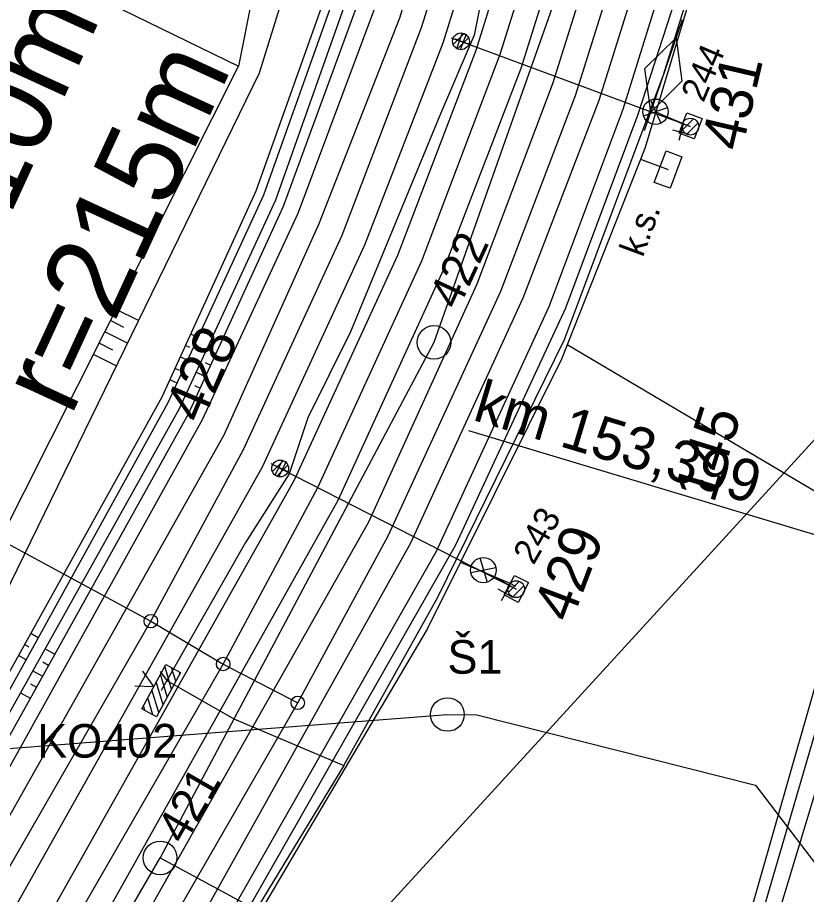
# Model space of a CAD drawing. Extents: x -598638 to -597933, y -1164002 to -1161904.
# Drawn here: x -598318.5 to -598271.6, y -1163425.1 to -1163372.9 of the extents above; entities that cross this region are included whole.
import ezdxf

# ---------------------------------------------------------------- set-up
doc = ezdxf.new("R2010")
doc.units = 0
for name, color, linetype in [('Vrstva 1', 7, 'Continuous'), ('Vrstva 11', 7, 'Continuous'), ('Vrstva 12', 7, 'Continuous'), ('Vrstva 25', 7, 'Continuous'), ('Vrstva 26', 7, 'Continuous'), ('Vrstva 28', 7, 'Continuous'), ('Vrstva 35', 7, 'Continuous'), ('Vrstva 4', 7, 'Continuous'), ('Vrstva 43', 7, 'Continuous'), ('Vrstva 44', 7, 'Continuous'), ('Vrstva 48', 7, 'Continuous'), ('Vrstva 49', 7, 'Continuous'), ('Vrstva 51', 7, 'Continuous'), ('Vrstva 63', 7, 'Continuous'), ('Vrstva 7', 7, 'Continuous')]:
    doc.layers.add(name, color=color, linetype=linetype)

msp = doc.modelspace()

# ---------------------------------------------------------------- linework, layer by layer
at = {"layer": 'Vrstva 1'}
for points in [[(-598310.615, -1163408.802), (-598305.104, -1163398.594), (-598299.235, -1163385.843), (-598294.508, -1163373.505), (-598290.948, -1163362.176)], [(-598306.313, -1163411.351), (-598300.676, -1163400.85), (-598294.505, -1163387.377), (-598289.829, -1163375.091), (-598286.211, -1163363.553)], [(-598301.875, -1163413.661), (-598296.503, -1163403.727), (-598289.8, -1163389.175), (-598285.367, -1163377.539), (-598281.438, -1163365.04)], [(-598373.865, -1163374.549), (-598310.615, -1163408.802), (-598306.313, -1163411.351), (-598301.875, -1163413.661)], [(-598393.834, -1163553.208), (-598373.143, -1163517.281), (-598345.734, -1163469.728), (-598320.048, -1163425.17), (-598310.615, -1163408.802)], [(-598390.948, -1163558.179), (-598390.161, -1163556.813), (-598368.813, -1163519.747), (-598341.41, -1163472.227), (-598315.714, -1163427.65), (-598306.313, -1163411.351)], [(-598386.661, -1163560.816), (-598364.213, -1163521.839), (-598337.049, -1163474.718), (-598311.511, -1163430.389), (-598301.875, -1163413.661)]]:
    msp.add_lwpolyline(points, dxfattribs=at)
for centre in [(-598310.615, -1163408.802), (-598306.313, -1163411.351), (-598301.875, -1163413.661)]:
    msp.add_circle(centre, 0.4, dxfattribs=at)
at = {"layer": 'Vrstva 11'}
for p, q in [((-598292.631, -1163374.504), (-598291.985, -1163373.858)), ((-598292.371, -1163374.774), (-598291.716, -1163374.119)), ((-598278.991, -1163379.574), (-598278.345, -1163378.928)), ((-598278.731, -1163379.844), (-598278.076, -1163379.189)), ((-598303.381, -1163399.904), (-598302.735, -1163399.258)), ((-598303.121, -1163400.174), (-598302.466, -1163399.519)), ((-598289.351, -1163407.084), (-598288.705, -1163406.438)), ((-598289.091, -1163407.354), (-598288.436, -1163406.699))]:
    msp.add_line(p, q, dxfattribs=at)
for points in [[(-598278.53, -1163379.39), (-598292.17, -1163374.32)], [(-598288.89, -1163406.9), (-598302.92, -1163399.72)]]:
    msp.add_lwpolyline(points, dxfattribs=at)
for centre in [(-598292.17, -1163374.32), (-598278.53, -1163379.39), (-598302.92, -1163399.72), (-598288.89, -1163406.9)]:
    msp.add_circle(centre, 0.5, dxfattribs=at)
at = {"layer": 'Vrstva 12'}
for points in [[(-598279.19, -1163379.79), (-598278.73, -1163378.58), (-598277.82, -1163378.91), (-598278.3, -1163380.12), (-598279.19, -1163379.79)], [(-598289.61, -1163407.23), (-598288.98, -1163406.08), (-598288.16, -1163406.51), (-598288.76, -1163407.69), (-598289.61, -1163407.23)]]:
    msp.add_lwpolyline(points, dxfattribs=at)
at = {"layer": 'Vrstva 25'}
for p, q in [((-598281.318, -1163378.742), (-598279.889, -1163378.261)), ((-598280.906, -1163377.814), (-598280.287, -1163379.19)), ((-598279.91, -1163378.802), (-598278.53, -1163379.39)), ((-598291.055, -1163405.046), (-598290.609, -1163406.487)), ((-598291.578, -1163405.916), (-598290.101, -1163405.614)), ((-598290.188, -1163406.148), (-598288.89, -1163406.9))]:
    msp.add_line(p, q, dxfattribs=at)
msp.add_lwpolyline([(-598279.734, -1163383.058), (-598280.671, -1163382.709), (-598279.974, -1163380.834), (-598279.037, -1163381.183), (-598279.734, -1163383.058)], dxfattribs=at)
for centre in [(-598280.603, -1163378.505), (-598290.839, -1163405.768)]:
    msp.add_circle(centre, 0.754, dxfattribs=at)
at = {"layer": 'Vrstva 26'}
for points in [[(-598273.816, -1163355.578), (-598274.288, -1163357.583), (-598281.234, -1163380.697), (-598286.2, -1163393.216), (-598294.185, -1163409.285), (-598301.289, -1163421.306), (-598307.089, -1163431.139)], [(-598280.577, -1163378.511), (-598278.992, -1163379.224), (-598278.678, -1163379.312)], [(-598281.501, -1163381.336), (-598279.854, -1163381.946)], [(-598285.855, -1163392.347), (-598269.505, -1163402.021), (-598268.731, -1163402.266), (-598252.259, -1163406.667), (-598250.635, -1163407.319), (-598251.158, -1163408.595)], [(-598292.202, -1163405.294), (-598289.268, -1163406.549), (-598288.926, -1163406.729)]]:
    msp.add_lwpolyline(points, dxfattribs=at)
at = {"layer": 'Vrstva 28'}
for p, q in [((-598281.259, -1163379.623), (-598279, -1163373.017)), ((-598281.231, -1163375.944), (-598279.377, -1163374.118)), ((-598279.377, -1163374.118), (-598279.028, -1163376.697)), ((-598280.883, -1163378.522), (-598281.231, -1163375.944)), ((-598279.028, -1163376.697), (-598280.883, -1163378.522)), ((-598309.384, -1163412.842), (-598309.789, -1163411.487)), ((-598309.133, -1163412.375), (-598309.375, -1163411.563)), ((-598309.637, -1163413.309), (-598310.041, -1163411.955)), ((-598308.881, -1163411.909), (-598308.909, -1163411.815)), ((-598309.889, -1163413.775), (-598310.294, -1163412.42)), ((-598310.141, -1163414.242), (-598310.546, -1163412.887)), ((-598310.495, -1163414.367), (-598310.798, -1163413.354)), ((-598310.962, -1163414.115), (-598311.05, -1163413.821))]:
    msp.add_line(p, q, dxfattribs=at)
for points in [[(-598280.87, -1163335.69), (-598282.75, -1163342.88), (-598282.94, -1163344.95), (-598283.45, -1163346.41), (-598287.18, -1163358.85), (-598290.82, -1163371.16), (-598291.38, -1163373.96), (-598293.38, -1163378.64), (-598298.74, -1163391.6), (-598301.27, -1163396.71), (-598302.38, -1163400.04), (-598304.98, -1163404.12), (-598309.67, -1163412.34), (-598310, -1163412.93)], [(-598310.06, -1163411.8), (-598309.67, -1163412.34), (-598305.68, -1163414.61), (-598299.13, -1163417.38), (-598293.55, -1163407.38), (-598286.02, -1163392.05), (-598280.13, -1163376.32), (-598275.56, -1163361.58), (-598274.1, -1163355.29), (-598270.65, -1163341.78), (-598271.66, -1163341.69), (-598271.75, -1163341.22)], [(-598311.153, -1163414.012), (-598309.728, -1163411.373), (-598308.848, -1163411.848), (-598310.273, -1163414.487), (-598311.153, -1163414.012)], [(-598311.558, -1163412.657), (-598310.441, -1163412.692), (-598311.082, -1163411.777)], [(-598299.13, -1163417.38), (-598305.71, -1163428.21), (-598313.95, -1163442.64), (-598320.15, -1163459.12), (-598330, -1163482.52), (-598335.96, -1163491.26), (-598347.35, -1163507.42), (-598355.33, -1163518.86), (-598362.35, -1163528.57), (-598373.82, -1163547.05), (-598380.92, -1163559.06), (-598385.36, -1163568.33)]]:
    msp.add_lwpolyline(points, dxfattribs=at)
msp.add_lwpolyline([(-598311.153, -1163414.012), (-598309.728, -1163411.373), (-598308.848, -1163411.848), (-598310.273, -1163414.487)], close=True, dxfattribs=at)
at = {"layer": 'Vrstva 35'}
msp.add_lwpolyline([(-598310.06, -1163411.8), (-598309.67, -1163412.34), (-598305.68, -1163414.61), (-598299.13, -1163417.38)], dxfattribs=at)
at = {"layer": 'Vrstva 4'}
for points in [[(-598398.167, -1163553.239), (-598376.487, -1163515.918), (-598348.795, -1163467.979), (-598339.716, -1163452.202), (-598323.266, -1163423.236), (-598308.372, -1163396.471), (-598302.715, -1163384.123), (-598298.324, -1163372.137), (-598289.593, -1163344.221), (-598282.967, -1163321.229), (-598274.797, -1163290.285), (-598269.404, -1163272.781), (-598266.519, -1163258.633), (-598263.896, -1163241.651), (-598261.185, -1163218.05), (-598260.503, -1163217.001), (-598259.092, -1163201.513), (-598258.163, -1163186.176), (-598256.557, -1163141.317), (-598256.485, -1163129.008), (-598255.651, -1163108.451), (-598254.34, -1163087.718), (-598253.319, -1163075.132)], [(-598307.376, -1163503.64), (-598306.256, -1163500.72), (-598304.527, -1163496.743), (-598299.478, -1163486.144), (-598290.117, -1163465.204), (-598280.795, -1163442.724), (-598274.814, -1163425.66), (-598269.09, -1163405.616), (-598262.907, -1163380.487), (-598260.225, -1163366.071), (-598256.638, -1163342.661), (-598254.612, -1163322.432), (-598252.977, -1163304.928), (-598251.437, -1163287.268), (-598250.068, -1163266.224), (-598248.818, -1163245.446), (-598248.467, -1163214.545), (-598248.623, -1163173.63), (-598248.072, -1163131.254), (-598247.596, -1163128.349)], [(-598388.69, -1163572.819), (-598382.701, -1163561.089), (-598361.383, -1163524.292), (-598334.6, -1163477.579), (-598308.353, -1163432.12), (-598292.471, -1163404.257), (-598285.937, -1163390.16), (-598281.631, -1163378.652), (-598277.216, -1163365.008), (-598272.579, -1163348.284), (-598269.387, -1163336.75), (-598267.113, -1163324.869), (-598262.674, -1163291.919), (-598258.642, -1163259.137), (-598254.182, -1163220.99), (-598251.647, -1163201.068), (-598250.766, -1163187.503), (-598249.671, -1163144.519), (-598248.922, -1163130.776), (-598248.69, -1163130.313)]]:
    msp.add_lwpolyline(points, dxfattribs=at)
at = {"layer": 'Vrstva 43'}
for centre in [(-598293.775, -1163392.227), (-598292.973, -1163414.355), (-598310.061, -1163422.881)]:
    msp.add_circle(centre, 1, dxfattribs=at)
at = {"layer": 'Vrstva 44'}
for points in [[(-598275.426, -1163334.13), (-598284.517, -1163365.994), (-598293.775, -1163392.227), (-598310.061, -1163422.881)], [(-598403.637, -1163432.342), (-598346.555, -1163418.577), (-598345.216, -1163418.65), (-598343.663, -1163418.367), (-598342.098, -1163418.162), (-598292.973, -1163414.355), (-598291.233, -1163414.37), (-598274.654, -1163418.559), (-598263.203, -1163433.575), (-598253.773, -1163465.608), (-598253.123, -1163466.538), (-598245.997, -1163476.61), (-598234.314, -1163480.567), (-598232.066, -1163480.596), (-598231.165, -1163480.525)], [(-598351.577, -1163494.88), (-598326.623, -1163451.361), (-598310.061, -1163422.881), (-598300.732, -1163427.915)]]:
    msp.add_lwpolyline(points, dxfattribs=at)
at = {"layer": 'Vrstva 48'}
for p, q in [((-598311.352, -1163390.931), (-598312.682, -1163390.261)), ((-598312.217, -1163391.335), (-598313.019, -1163390.931)), ((-598312.011, -1163392.279), (-598313.356, -1163391.601)), ((-598307.797, -1163391.928), (-598308.236, -1163391.728)), ((-598312.881, -1163392.68), (-598313.694, -1163392.271)), ((-598308.285, -1163392.53), (-598308.547, -1163392.411)), ((-598307.291, -1163392.638), (-598306.733, -1163392.893)), ((-598312.669, -1163393.627), (-598314.031, -1163392.941)), ((-598308.425, -1163393.29), (-598308.857, -1163393.093)), ((-598308.911, -1163393.893), (-598309.168, -1163393.776)), ((-598307.382, -1163393.421), (-598307.045, -1163393.575)), ((-598307.921, -1163393.999), (-598307.358, -1163394.257)), ((-598309.053, -1163394.653), (-598309.479, -1163394.458)), ((-598308.009, -1163394.784), (-598307.67, -1163394.939)), ((-598308.55, -1163395.361), (-598307.982, -1163395.621)), ((-598317.305, -1163409.786), (-598317.756, -1163409.535)), ((-598317.848, -1163410.342), (-598318.121, -1163410.191)), ((-598316.906, -1163410.444), (-598316.327, -1163410.766)), ((-598318.03, -1163411.099), (-598318.485, -1163410.846)), ((-598317.04, -1163411.228), (-598316.692, -1163411.422)), ((-598317.638, -1163411.754), (-598317.056, -1163412.077)), ((-598317.77, -1163412.538), (-598317.421, -1163412.732)), ((-598318.369, -1163413.063), (-598317.786, -1163413.388))]:
    msp.add_line(p, q, dxfattribs=at)
at = {"layer": 'Vrstva 49'}
for p in [(-598298.967, -1163343.623), (-598322.823, -1163410.399)]:
    msp.add_line(p, (-598305.395, -1163375.792), dxfattribs=at)
for points in [[(-598350.075, -1163469.161), (-598350.962, -1163468.642), (-598341.128, -1163451.449), (-598324.91, -1163422.41), (-598309.936, -1163395.461), (-598304.358, -1163383.215), (-598300.139, -1163371.399), (-598292.224, -1163343.911), (-598285.916, -1163320.98), (-598277.492, -1163289.124), (-598272.642, -1163272.084), (-598269.771, -1163257.778), (-598267.544, -1163241.285), (-598265.728, -1163218.657), (-598264.511, -1163217.412), (-598261.185, -1163218.05)], [(-598350.962, -1163468.642), (-598340.803, -1163451.583), (-598324.406, -1163422.648), (-598309.58, -1163395.796), (-598303.887, -1163383.446), (-598299.666, -1163371.582), (-598291.401, -1163343.859), (-598285.02, -1163321.209), (-598276.751, -1163289.495), (-598271.739, -1163271.843), (-598268.729, -1163258.218), (-598266.553, -1163241.22), (-598264.463, -1163218.64)], [(-598350.075, -1163469.161), (-598340.252, -1163451.87), (-598323.84, -1163422.849), (-598308.915, -1163396.15), (-598303.181, -1163383.749), (-598299.003, -1163371.924), (-598290.374, -1163343.997), (-598283.872, -1163321.586), (-598275.648, -1163289.867), (-598270.185, -1163272.379), (-598267.391, -1163258.396), (-598265.172, -1163241.341), (-598262.635, -1163218.663), (-598264.463, -1163218.64)], [(-598346.31, -1163359.045), (-598341.587, -1163361.65), (-598323.035, -1163367.197), (-598305.395, -1163375.792)], [(-598321.354, -1163411.417), (-598304.154, -1163376.186), (-598299.445, -1163361.058)]]:
    msp.add_lwpolyline(points, dxfattribs=at)
at = {"layer": 'Vrstva 51'}
for points in [[(-598397.431, -1163553.318), (-598375.745, -1163515.943), (-598348.098, -1163468.333), (-598322.38, -1163423.533), (-598307.542, -1163396.818), (-598301.86, -1163384.541), (-598297.285, -1163372.341), (-598293.283, -1163359.379), (-598288.845, -1163344.448), (-598282.25, -1163321.235), (-598273.825, -1163290.423), (-598265.756, -1163258.778), (-598260.545, -1163219.203), (-598259.744, -1163217.171), (-598258.57, -1163201.891), (-598257.659, -1163186.255), (-598256.038, -1163142.193), (-598255.793, -1163128.623), (-598255.065, -1163108.27), (-598253.781, -1163088.998), (-598252.62, -1163075.466)], [(-598396.078, -1163554.151), (-598374.443, -1163516.599), (-598347.031, -1163469.014), (-598321.218, -1163424.261), (-598306.253, -1163397.723), (-598300.608, -1163385.153), (-598295.814, -1163372.93), (-598291.849, -1163359.988), (-598287.46, -1163344.41), (-598281.154, -1163322.32), (-598272.412, -1163291.197), (-598264.229, -1163259.135), (-598258.972, -1163219.27), (-598257.327, -1163201.644), (-598256.369, -1163186.491), (-598254.79, -1163142.649), (-598254.397, -1163128.629), (-598253.571, -1163108.317), (-598252.585, -1163090.153), (-598250.983, -1163076.012)], [(-598384.985, -1163560.822), (-598363.176, -1163523.063), (-598335.955, -1163475.581), (-598310.179, -1163431.066), (-598295.149, -1163404.135), (-598288.465, -1163389.583), (-598283.96, -1163377.815), (-598279.772, -1163364.473), (-598275.196, -1163348.33), (-598271.933, -1163336.198), (-598269.31, -1163324.265), (-598265.084, -1163292.029), (-598261.053, -1163259.678), (-598256.104, -1163220.296), (-598254.426, -1163201.671), (-598253.667, -1163187.936), (-598252.018, -1163143.494), (-598251.534, -1163128.863), (-598250.791, -1163108.998), (-598250.069, -1163094.383), (-598248.218, -1163076.729)], [(-598298.888, -1163486.593), (-598289.113, -1163465.583), (-598279.905, -1163442.964), (-598274.107, -1163425.699), (-598268.268, -1163405.757), (-598262.238, -1163380.596), (-598259.701, -1163366.461), (-598255.999, -1163342.847), (-598253.859, -1163322.319), (-598252.407, -1163304.609), (-598250.982, -1163286.31), (-598249.458, -1163266.6), (-598248.128, -1163245.447), (-598247.963, -1163214.31), (-598248.01, -1163173.778), (-598247.475, -1163130.652), (-598247.596, -1163128.349), (-598246.685, -1163112.866), (-598245.177, -1163096.514), (-598242.921, -1163076.624)], [(-598389.422, -1163572.47), (-598383.242, -1163561.018), (-598361.933, -1163523.985), (-598335.337, -1163477.363), (-598309.065, -1163431.797), (-598293.626, -1163404.644), (-598286.924, -1163390.082), (-598282.523, -1163378.361), (-598278.252, -1163364.663), (-598273.758, -1163348.557), (-598270.372, -1163336.656), (-598267.892, -1163324.623), (-598263.657, -1163291.858), (-598259.724, -1163259.57), (-598255.007, -1163220.516), (-598252.865, -1163201.196), (-598252.034, -1163187.935), (-598250.643, -1163143.798), (-598250.023, -1163129.244), (-598249.184, -1163109.078), (-598248.423, -1163094.475), (-598246.693, -1163077.089)], [(-598305.922, -1163504.285), (-598297.335, -1163487.137), (-598287.92, -1163465.981), (-598279.035, -1163443.103), (-598273.208, -1163425.978), (-598267.2, -1163406.108), (-598261.011, -1163380.887), (-598258.166, -1163366.304), (-598254.569, -1163343.143), (-598252.435, -1163322.084), (-598250.965, -1163305.051), (-598249.488, -1163286.133), (-598247.962, -1163266.793), (-598246.718, -1163245.404), (-598246.637, -1163214.417), (-598246.633, -1163173.748), (-598246.347, -1163129.422), (-598245.484, -1163112.939), (-598244.076, -1163096.672), (-598241.475, -1163076.865)], [(-598405.752, -1163584.856), (-598406.565, -1163584.53), (-598399.621, -1163567.58), (-598392.991, -1163554.623), (-598370.643, -1163515.908), (-598344.594, -1163470.689), (-598318.975, -1163426.348), (-598303.98, -1163399.626), (-598297.883, -1163386.424), (-598293.238, -1163374.41), (-598289.078, -1163361.082), (-598284.443, -1163344.622), (-598278.418, -1163323.499), (-598273.781, -1163306.93), (-598268.859, -1163289.076)], [(-598405.752, -1163584.856), (-598398.056, -1163568.29), (-598390.909, -1163555.148), (-598369.148, -1163517.525), (-598342.954, -1163471.89), (-598317.093, -1163427.101), (-598302.088, -1163400.435), (-598295.928, -1163387.037), (-598291.26, -1163374.845), (-598287.219, -1163361.857), (-598282.441, -1163344.932), (-598276.551, -1163323.978), (-598272.024, -1163307.744), (-598269.633, -1163298.161), (-598267.957, -1163289.279), (-598268.859, -1163289.076)], [(-598427.315, -1163664.7), (-598428.18, -1163664.394), (-598425.636, -1163654.614), (-598418.444, -1163627.396), (-598410.117, -1163604.122), (-598400.961, -1163581.084), (-598395.464, -1163569.593), (-598389.92, -1163559.339), (-598367.418, -1163520.243), (-598340.118, -1163472.9), (-598314.456, -1163428.342), (-598299.482, -1163401.608), (-598293.182, -1163387.859), (-598288.581, -1163375.919), (-598284.449, -1163362.711), (-598279.879, -1163346.369), (-598272.886, -1163321.804)], [(-598427.315, -1163664.7), (-598423.952, -1163654.666), (-598416.386, -1163628.209), (-598407.715, -1163605.193), (-598398.502, -1163582.119), (-598393.545, -1163570.609), (-598388.107, -1163560.38), (-598365.543, -1163521.215), (-598338.352, -1163474.013), (-598312.732, -1163429.553), (-598297.643, -1163402.904), (-598291.214, -1163388.734), (-598286.704, -1163376.829), (-598282.472, -1163363.328), (-598277.874, -1163346.939), (-598274.73, -1163335.645), (-598271.957, -1163322.057), (-598272.886, -1163321.804)]]:
    msp.add_lwpolyline(points, dxfattribs=at)
at = {"layer": 'Vrstva 63'}
msp.add_line((-598304.703, -1163434.652), (-598243.435, -1163367.735), dxfattribs=at)
at = {"layer": 'Vrstva 7'}
for p, q in [((-598292.102, -1163373.822), (-598292.43, -1163374.766)), ((-598291.857, -1163373.899), (-598292.215, -1163374.833)), ((-598291.794, -1163374.458), (-598292.738, -1163374.13)), ((-598291.569, -1163374.545), (-598292.503, -1163374.187)), ((-598278.955, -1163379.245), (-598279.221, -1163380.209)), ((-598278.606, -1163379.86), (-598279.57, -1163379.594)), ((-598291.713, -1163397.458), (-598263.021, -1163406.09)), ((-598302.567, -1163399.901), (-598303.459, -1163399.449)), ((-598302.787, -1163399.229), (-598303.239, -1163400.121)), ((-598302.34, -1163399.986), (-598303.234, -1163399.538)), ((-598302.563, -1163399.315), (-598303.011, -1163400.209)), ((-598289.093, -1163407.396), (-598289.967, -1163406.91)), ((-598289.287, -1163406.716), (-598289.773, -1163407.59))]:
    msp.add_line(p, q, dxfattribs=at)

# ---------------------------------------------------------------- texts
at = {"layer": 'Vrstva 1'}
for s, rotation, p in [('r=210m', 65.3909, (-598323.118, -1163393.719)), ('r=215m', 65.2681, (-598315.367, -1163396.686))]:
    msp.add_text(s, height=5, rotation=rotation, dxfattribs=at).set_placement(p)
at = {"layer": 'Vrstva 11'}
for s, rotation, p in [('431', 76.8672, (-598275.473, -1163380.919)), ('428', 66.9105, (-598307.576, -1163397.135)), ('145', 72.778, (-598277.13, -1163401.846)), ('429', 69.2195, (-598285.615, -1163408.975))]:
    msp.add_text(s, height=2.5, rotation=rotation, dxfattribs=at).set_placement(p)
at = {"layer": 'Vrstva 25'}
for s, rotation, p in [('244', 66.9335, (-598277.753, -1163378.008)), ('k.s.', 69.619, (-598281.361, -1163387.211)), ('243', 59.9175, (-598287.854, -1163405.518))]:
    msp.add_text(s, height=1.5, rotation=rotation, dxfattribs=at).set_placement(p)
at = {"layer": 'Vrstva 28'}
msp.add_text('KO402', height=2, rotation=0.1145, dxfattribs=at).set_placement((-598317.369, -1163416.929))
at = {"layer": 'Vrstva 43'}
for s, rotation, p in [('422', 65.2681, (-598292.334, -1163390.353)), ('421', 60.0563, (-598308.62, -1163422.16))]:
    msp.add_text(s, height=2, rotation=rotation, dxfattribs=at).set_placement(p)
msp.add_text('Š1', height=2, dxfattribs=at).set_placement((-598292.973, -1163411.928))
at = {"layer": 'Vrstva 7'}
msp.add_text('km 153,399', height=2.5, rotation=343.2554, dxfattribs=at).set_placement((-598291.537, -1163396.822))

doc.saveas('drawing.dxf')
